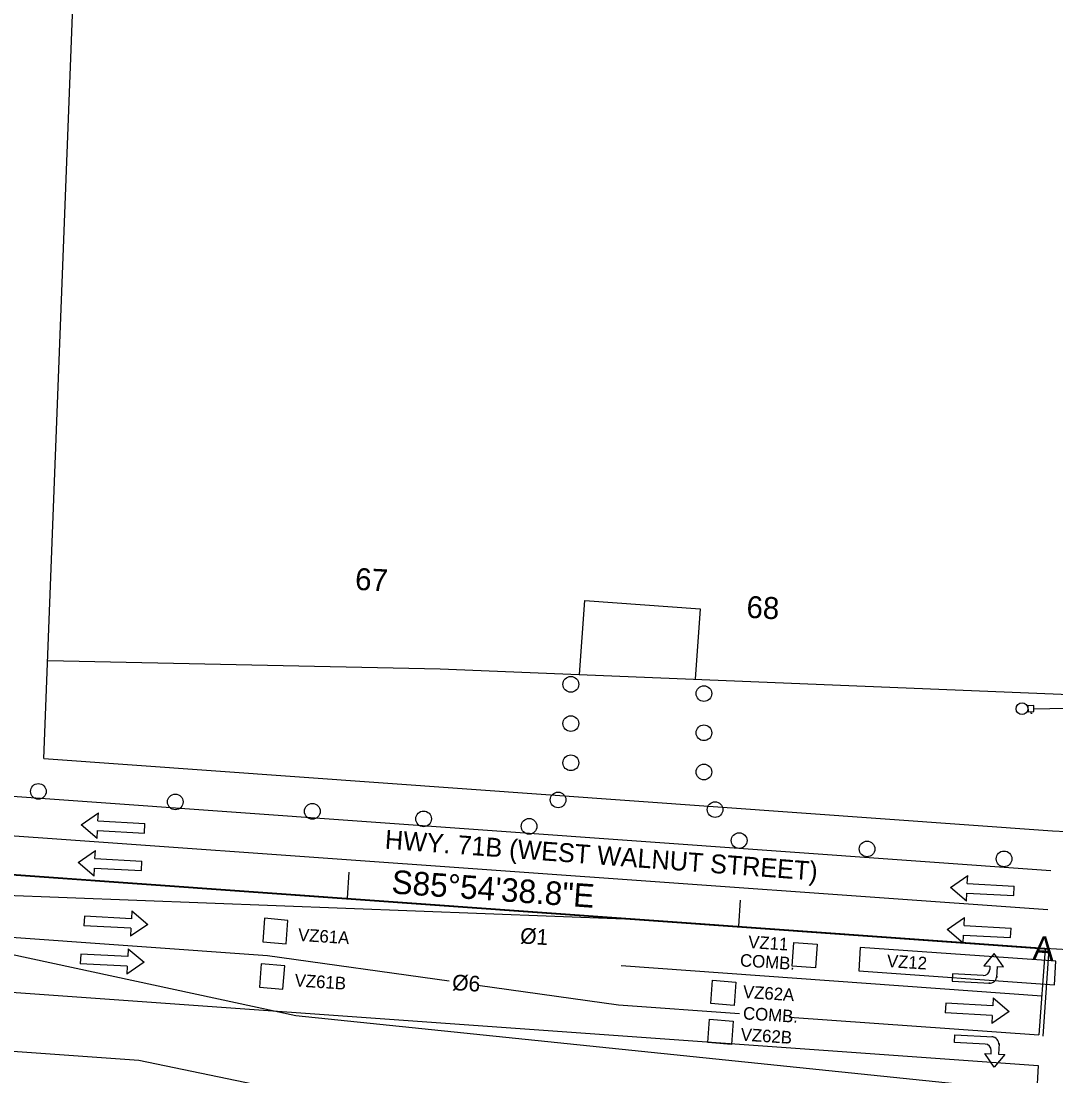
# Model space of a CAD drawing. Extents: x 679444 to 687671, y 733868 to 736107.
# Drawn here: x 685888.8 to 686152.6, y 734818.8 to 735087.7 of the extents above; entities that cross this region are included whole.
import ezdxf

# ---------------------------------------------------------------- set-up
doc = ezdxf.new("R2010")
doc.units = 0
for name, color, linetype in [('$', 7, 'Continuous'), ('BASE', 7, 'Continuous'), ('Clipping Boundary', 7, 'Continuous'), ('MOT Stage 1', 7, 'Continuous'), ('MOT Stage 1 Lanes', 7, 'Continuous'), ('R_Horz Alg', 7, 'Continuous'), ('R_Horz Alg Station', 7, 'Continuous'), ('RW-EX', 7, 'Continuous'), ('RW-PR', 7, 'Continuous'), ('SIGNAL-PLAN VIEW LABLES', 7, 'Continuous'), ('SIGNAL-PR$', 7, 'Continuous'), ('TITEXT', 7, 'Continuous'), ('Video-Zones-pr', 7, 'Continuous')]:
    doc.layers.add(name, color=color, linetype=linetype)

# ---------------------------------------------------------------- blocks, each defined once
blk = doc.blocks.new('BAREL_1780')
at = {"layer": 'MOT Stage 1'}
blk.add_circle((0, 0.01), 2.88, dxfattribs=at)
blk = doc.blocks.new('BAREL_1781')
at = {"layer": 'MOT Stage 1'}
blk.add_circle((0, 0.01), 2.88, dxfattribs=at)
blk = doc.blocks.new('BAREL_1782')
at = {"layer": 'MOT Stage 1'}
blk.add_circle((0, 0.01), 2.88, dxfattribs=at)
blk = doc.blocks.new('BAREL_1783')
at = {"layer": 'MOT Stage 1'}
blk.add_circle((0, 0.01), 2.88, dxfattribs=at)
blk = doc.blocks.new('BAREL_1784')
at = {"layer": 'MOT Stage 1'}
blk.add_circle((0, 0.01), 2.88, dxfattribs=at)
blk = doc.blocks.new('BAREL_1785')
at = {"layer": 'MOT Stage 1'}
blk.add_circle((0, 0.01), 2.88, dxfattribs=at)
blk = doc.blocks.new('SARROW_207')
at = {"layer": 'MOT Stage 1'}
for p, q in [((0, 0), (-6, 0)), ((0, -29.42), (0, 0)), ((-6, -29.42), (-6, 0)), ((-6, -29.42), (-11, -29.42)), ((-3, -39.81), (-11, -29.42)), ((5, -29.42), (-3, -39.81)), ((5, -29.42), (0, -29.42))]:
    blk.add_line(p, q, dxfattribs=at)
blk = doc.blocks.new('SARROW_208')
at = {"layer": 'MOT Stage 1'}
for p, q in [((-6, -29.42), (-6, 0)), ((0, 0), (-6, 0)), ((0, -29.42), (0, 0)), ((-6, -29.42), (-11, -29.42)), ((-3, -39.81), (-11, -29.42)), ((5, -29.42), (-3, -39.81)), ((5, -29.42), (0, -29.42))]:
    blk.add_line(p, q, dxfattribs=at)
blk = doc.blocks.new('SARROW_209')
at = {"layer": 'MOT Stage 1'}
for p, q in [((-6, -29.42), (-6, 0)), ((0, 0), (-6, 0)), ((0, -29.42), (0, 0)), ((-6, -29.42), (-11, -29.42)), ((-3, -39.81), (-11, -29.42)), ((5, -29.42), (-3, -39.81)), ((5, -29.42), (0, -29.42))]:
    blk.add_line(p, q, dxfattribs=at)
blk = doc.blocks.new('SARROW_213')
at = {"layer": 'MOT Stage 1'}
for p, q in [((0, 0), (-6, 0)), ((0, -29.42), (0, 0)), ((-6, -29.42), (-6, 0)), ((-6, -29.42), (-11, -29.42)), ((-3, -39.81), (-11, -29.42)), ((5, -29.42), (-3, -39.81)), ((5, -29.42), (0, -29.42))]:
    blk.add_line(p, q, dxfattribs=at)
blk = doc.blocks.new('SARROW_214')
at = {"layer": 'MOT Stage 1'}
for p, q in [((-6, -29.42), (-6, 0)), ((0, 0), (-6, 0)), ((0, -29.42), (0, 0)), ((-6, -29.42), (-11, -29.42)), ((-3, -39.81), (-11, -29.42)), ((5, -29.42), (-3, -39.81)), ((5, -29.42), (0, -29.42))]:
    blk.add_line(p, q, dxfattribs=at)
blk = doc.blocks.new('SARROW_215')
at = {"layer": 'MOT Stage 1'}
for p, q in [((0, 0), (-6, 0)), ((0, -29.42), (0, 0)), ((-6, -29.42), (-6, 0)), ((-6, -29.42), (-11, -29.42)), ((-3, -39.81), (-11, -29.42)), ((5, -29.42), (-3, -39.81)), ((5, -29.42), (0, -29.42))]:
    blk.add_line(p, q, dxfattribs=at)
blk = doc.blocks.new('SARROW_216')
at = {"layer": 'MOT Stage 1'}
for p, q in [((0, 0), (-6, 0)), ((0, -29.42), (0, 0)), ((-6, -29.42), (-6, 0)), ((-6, -29.42), (-11, -29.42)), ((-3, -39.81), (-11, -29.42)), ((5, -29.42), (-3, -39.81)), ((5, -29.42), (0, -29.42))]:
    blk.add_line(p, q, dxfattribs=at)
blk = doc.blocks.new('BAREL_1819')
at = {"layer": 'MOT Stage 1'}
blk.add_circle((0, 0.01), 2.88, dxfattribs=at)
blk = doc.blocks.new('BAREL_1820')
at = {"layer": 'MOT Stage 1'}
blk.add_circle((0, 0.01), 2.88, dxfattribs=at)
blk = doc.blocks.new('BAREL_1821')
at = {"layer": 'MOT Stage 1'}
blk.add_circle((0, 0.01), 2.88, dxfattribs=at)
blk = doc.blocks.new('BAREL_1822')
at = {"layer": 'MOT Stage 1'}
blk.add_circle((0, 0.01), 2.88, dxfattribs=at)
blk = doc.blocks.new('BAREL_1868')
at = {"layer": 'MOT Stage 1'}
blk.add_circle((0, 0.01), 2.88, dxfattribs=at)
blk = doc.blocks.new('BAREL_1869')
at = {"layer": 'MOT Stage 1'}
blk.add_circle((0, 0.01), 2.88, dxfattribs=at)
blk = doc.blocks.new('BAREL_1911')
at = {"layer": 'MOT Stage 1'}
blk.add_circle((0, 0.01), 2.88, dxfattribs=at)
blk = doc.blocks.new('BAREL_1912')
at = {"layer": 'MOT Stage 1'}
blk.add_circle((0, 0.01), 2.88, dxfattribs=at)
blk = doc.blocks.new('BAREL_1913')
at = {"layer": 'MOT Stage 1'}
blk.add_circle((0, 0.01), 2.88, dxfattribs=at)
blk = doc.blocks.new('BAREL_1914')
at = {"layer": 'MOT Stage 1'}
blk.add_circle((0, 0.01), 2.88, dxfattribs=at)

msp = doc.modelspace()

# ---------------------------------------------------------------- linework, layer by layer
at = {"layer": '$'}
msp.add_circle((686143.95, 734912.42), 1.5, dxfattribs=at)
at = {"layer": 'Clipping Boundary'}
msp.add_lwpolyline([(685004.96, 734911.26), (685870.83, 734853.15), (685958.87, 734834.19), (686124.37, 734817.12), (686182.42, 734811.14), (686223.62, 734765.98), (686227.86, 734744.58), (686187.41, 734736.57), (684968, 734818.52)], close=True, dxfattribs=at)
at = {"layer": 'MOT Stage 1'}
for points in [[(686137.54, 734844.26), (686137.52, 734843.94), (686137.66, 734846.67), (686139.25, 734846.59), (686136.89, 734850.01), (686134.18, 734846.86), (686135.76, 734846.77), (686135.72, 734845.95)], [(686134.05, 734844.44), (686126.26, 734844.86), (686126.16, 734842.95)], [(686126.16, 734842.95), (686135.85, 734842.44), (686135.53, 734842.46)], [(686134.58, 734826.93), (686126.73, 734827.35), (686126.83, 734829.27)], [(686126.83, 734829.27), (686136.59, 734828.75), (686136.28, 734828.77)], [(686138.09, 734826.75), (686138.11, 734827.07), (686137.96, 734824.32), (686139.56, 734824.23), (686136.83, 734821.05), (686134.45, 734824.5), (686136.05, 734824.42), (686136.09, 734825.25)]]:
    msp.add_lwpolyline(points, dxfattribs=at)
for centre, radius, start, end in [((686134.13, 734846.03), 1.59, 266.9687, 356.9687), ((686135.63, 734844.36), 1.9, 266.9687, 356.9687), ((686136.17, 734826.85), 1.92, 356.9687, 86.9687), ((686134.49, 734825.34), 1.6, 356.9687, 86.9687)]:
    msp.add_arc(centre, radius, start, end, dxfattribs=at)
at = {"layer": 'MOT Stage 1 Lanes'}
for p, q in [((685868.12, 734865.51), (686042.67, 734858.89)), ((685867.4, 734855.54), (685951.66, 734849.51)), ((685951.66, 734849.51), (685997.9, 734843.02)), ((686005.21, 734841.99), (686041.1, 734836.95))]:
    msp.add_line(p, q, dxfattribs=at)
for points in [[(685869.96, 734891.29), (686151.25, 734871.18)], [(685869.25, 734881.32), (686150.53, 734861.21)], [(685868.53, 734871.34), (686150.82, 734851.16)], [(686149.82, 734851.23), (686148.25, 734829.29)], [(686150.82, 734851.16), (686149.23, 734828.94)], [(686041.81, 734846.92), (686148.96, 734839.26)], [(686041.1, 734836.95), (686071.94, 734834.74)], [(686084.72, 734833.83), (686148.25, 734829.29)]]:
    msp.add_lwpolyline(points, dxfattribs=at)
at = {"layer": 'R_Horz Alg Station'}
for p, q in [((685868.54, 734871.5), (686149.79, 734851.39)), ((686149.79, 734851.39), (686255.4, 734845.31))]:
    msp.add_line(p, q, dxfattribs=at)
for points in [[(685972.4, 734870.76), (685971.92, 734864.11)], [(686072.14, 734863.63), (686071.67, 734856.98)]]:
    msp.add_lwpolyline(points, dxfattribs=at)
at = {"layer": 'RW-EX'}
for p, q in [((685894.65, 734899.71), (685906.88, 735216.51)), ((685894.65, 734899.71), (686151.72, 734881.33)), ((686151.72, 734881.33), (686176.47, 734879.9)), ((685615.93, 734859.48), (686148.06, 734821.44)), ((686148.06, 734821.44), (686147.62, 734813.65))]:
    msp.add_line(p, q, dxfattribs=at)
at = {"layer": 'RW-PR'}
for p, q in [((686031.14, 734921.13), (686032.48, 734939.98)), ((686032.48, 734939.98), (686061.91, 734937.88)), ((686061.91, 734937.88), (686060.63, 734919.93))]:
    msp.add_line(p, q, dxfattribs=at)
for points in [[(685895.62, 734924.7), (685995.63, 734922.56), (686160.19, 734915.9)], [(685416.49, 734855.93), (685615.28, 734844.49), (685918.84, 734822.79), (685992.93, 734807.46), (686092.68, 734800.33), (686145.51, 734791.54), (686191.41, 734759.48), (686200.21, 734731.89), (686188.38, 734460.16), (686187.2, 734387.13), (686196.02, 734332.97)]]:
    msp.add_lwpolyline(points, dxfattribs=at)
at = {"layer": 'SIGNAL-PLAN VIEW LABLES'}
msp.add_lwpolyline([(686145.48, 734911.67), (686146.98, 734911.72), (686146.93, 734913.22), (686145.43, 734913.16)], close=True, dxfattribs=at)
for points in [[(686146.5, 734911.2), (686146.25, 734911.19), (686146.23, 734911.69)], [(686146.96, 734912.36), (686159.25, 734912.67)]]:
    msp.add_lwpolyline(points, dxfattribs=at)
at = {"layer": 'Video-Zones-pr'}
for points in [[(685956.42, 734852.49), (685956.84, 734858.47), (685950.87, 734858.99), (685950.44, 734853), (685956.42, 734852.49)], [(685950.04, 734847.4), (685949.61, 734841.41), (685955.59, 734840.9), (685956.02, 734846.89), (685950.04, 734847.4)], [(686064.61, 734837.27), (686065.03, 734843.26), (686071.01, 734842.75), (686070.59, 734836.76), (686064.61, 734837.27)], [(686070.3, 734832.81), (686069.88, 734826.82), (686063.9, 734827.33), (686064.32, 734833.32), (686070.3, 734832.81)]]:
    msp.add_lwpolyline(points, dxfattribs=at)
for points in [[(686091.33, 734846.39), (686085.34, 734846.82), (686085.77, 734852.8), (686091.75, 734852.38)], [(686152.56, 734848.03), (686102.68, 734851.58), (686102.33, 734845.59), (686152.21, 734842.04)]]:
    msp.add_lwpolyline(points, close=True, dxfattribs=at)

# ---------------------------------------------------------------- block references
at = {"layer": 'MOT Stage 1'}
for name, p, xscale, yscale, rotation in [('BAREL_1780', (686028.96, 734918.64), 0.6945420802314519, 0.6945420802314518, 87.04179557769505), ('BAREL_1781', (686062.88, 734916.29), 0.6945420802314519, 0.6945420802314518, 87.04179557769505), ('BAREL_1782', (686028.96, 734908.64), 0.6945420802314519, 0.6945420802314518, 87.04179557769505), ('BAREL_1784', (686062.88, 734906.29), 0.6945420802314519, 0.6945420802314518, 87.04179557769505), ('BAREL_1783', (686028.96, 734898.64), 0.6945420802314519, 0.6945420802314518, 87.04179557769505), ('BAREL_1785', (686062.88, 734896.29), 0.6945420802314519, 0.6945420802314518, 87.04179557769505), ('BAREL_1911', (685893.25, 734891.35), 0.6945420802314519, 0.6945420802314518, 87.04179557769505), ('BAREL_1912', (685928.15, 734888.67), 0.6945420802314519, 0.6945420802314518, 87.04179557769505), ('BAREL_1819', (686025.71, 734889.18), 0.6945420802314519, 0.6945420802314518, 87.04179557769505), ('BAREL_1913', (685963.07, 734886.27), 0.6945420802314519, 0.6945420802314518, 87.04179557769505), ('BAREL_1820', (686065.72, 734886.71), 0.6945420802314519, 0.6945420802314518, 87.04179557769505), ('SARROW_213', (685920.27, 734880.74), 0.40758735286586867, 0.4075873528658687, -93.03128829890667), ('BAREL_1914', (685991.43, 734884.35), 0.6945420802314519, 0.6945420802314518, 87.04179557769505), ('BAREL_1868', (686018.32, 734882.44), 0.6945420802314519, 0.6945420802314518, 87.04179557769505), ('BAREL_1869', (686071.86, 734878.81), 0.6945420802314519, 0.6945420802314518, 87.04179557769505), ('SARROW_214', (685919.51, 734871.16), 0.40758735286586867, 0.4075873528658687, -93.03128829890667), ('BAREL_1821', (686104.46, 734876.67), 0.6945420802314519, 0.6945420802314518, 87.04179557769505), ('BAREL_1822', (686139.37, 734874.15), 0.6945420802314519, 0.6945420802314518, 87.04179557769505), ('SARROW_208', (686141.85, 734864.78), 0.40758735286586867, 0.4075873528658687, -93.03128829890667), ('SARROW_215', (685904.97, 734859.53), 0.4075873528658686, 0.40758735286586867, 86.96871170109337), ('SARROW_207', (686141.01, 734854.06), 0.40758735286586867, 0.4075873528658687, -93.03128829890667), ('SARROW_216', (685904.03, 734849.85), 0.4075873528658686, 0.40758735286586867, 86.96871170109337), ('SARROW_209', (686124.51, 734837.32), 0.4075873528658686, 0.40758735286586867, 86.96871170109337)]:
    msp.add_blockref(name, p, dxfattribs=dict(at, xscale=xscale, yscale=yscale, rotation=rotation))

# ---------------------------------------------------------------- texts
at = {"layer": '$'}
for s, p in [('67', (685973.87, 734942.76)), ('68', (686073.62, 734935.63))]:
    msp.add_text(s, height=5.6, rotation=357.0415, dxfattribs=at).set_placement(p)
at = {"layer": 'BASE'}
msp.add_text('HWY. 71B (WEST WALNUT STREET)', height=4.8, rotation=355.7594, dxfattribs=at).set_placement((685981.44, 734876.76))
at = {"layer": 'R_Horz Alg'}
msp.add_text('A', height=6, rotation=356.3078, dxfattribs=at).set_placement((686146.6, 734848.59))
at = {"layer": 'R_Horz Alg Station'}
msp.add_text('S85%%d54\'38.8"E', height=6, rotation=355.9108, dxfattribs=at).set_placement((685983.13, 734865.35))
at = {"layer": 'SIGNAL-PR$'}
for s, p in [('VZ61A', (685959.34, 734853.25)), ('VZ11', (686074.07, 734851.43)), ('COMB.', (686071.99, 734846.75)), ('VZ12', (686109.42, 734846.58)), ('VZ61B', (685958.49, 734841.65)), ('VZ62A', (686072.74, 734838.71)), ('COMB.', (686072.75, 734833.25)), ('VZ62B', (686072.16, 734827.84))]:
    msp.add_text(s, height=3.2, rotation=356.2723, dxfattribs=at).set_placement(p)
at = {"layer": 'TITEXT'}
for s, p in [('%%C1', (686015.94, 734852.61)), ('%%C6', (685998.61, 734840.72))]:
    msp.add_text(s, height=4, rotation=356.2723, dxfattribs=at).set_placement(p)

doc.saveas('drawing.dxf')
